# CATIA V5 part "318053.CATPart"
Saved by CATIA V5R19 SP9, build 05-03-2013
Part number: 318053
Source: Unknown
Bounding box of the stored display mesh (mm): x -693.471 to 180, y 131 to 134, z 193.051 to 591
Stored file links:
  D:\16-SIL\kale oto\R19_V1\318053.CATPart
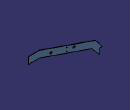
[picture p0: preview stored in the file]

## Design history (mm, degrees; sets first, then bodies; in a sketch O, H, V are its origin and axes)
Body1 "157\\127\\MANIFOLD_SOLID_BREP #80873" (main body)
  Solid1: solid without history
